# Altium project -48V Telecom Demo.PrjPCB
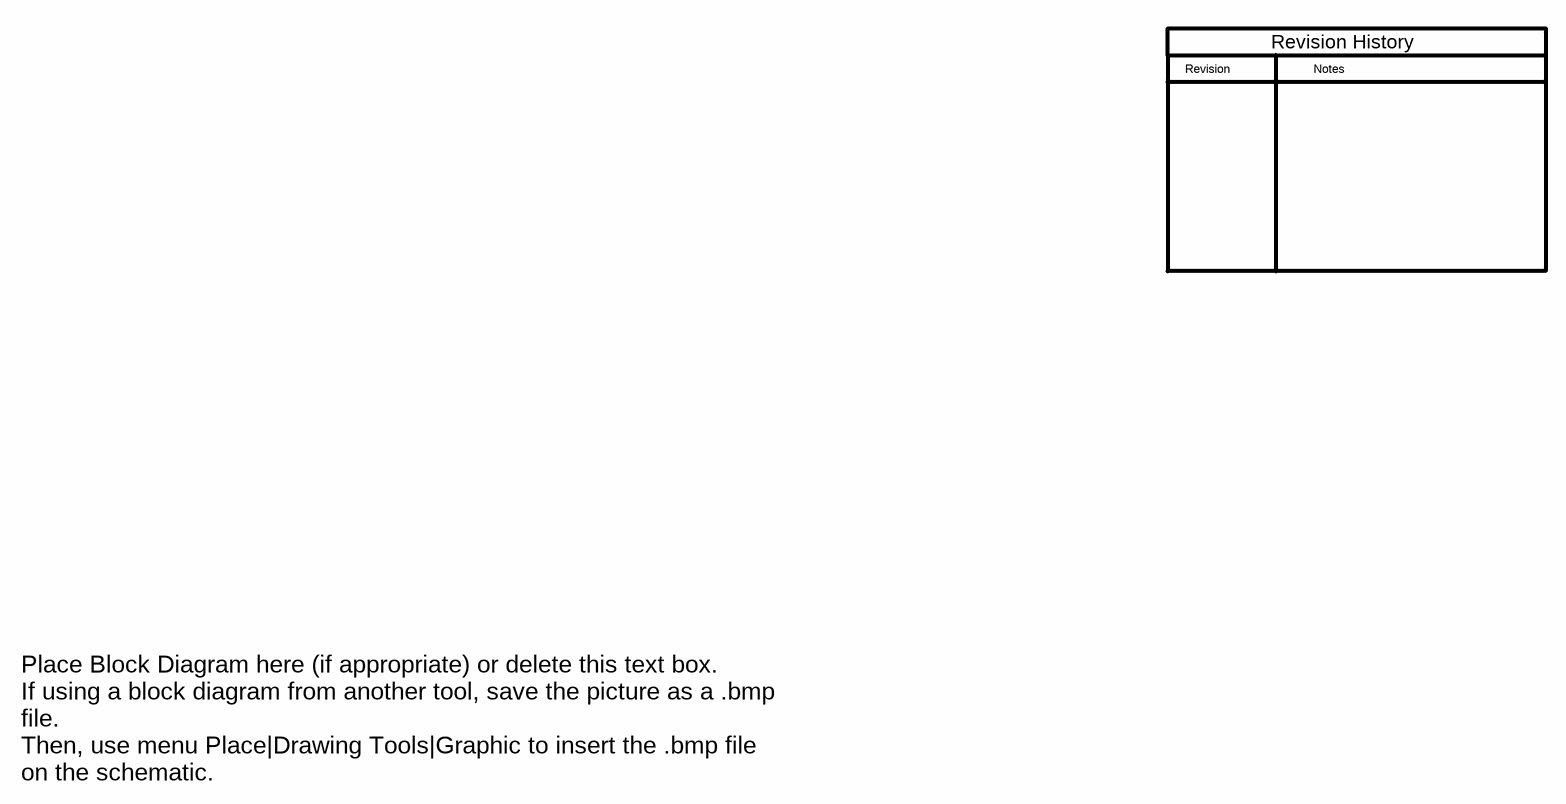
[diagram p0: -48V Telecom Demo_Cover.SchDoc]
TechSupport: http://e2e.ti.com; SCH_Rev: 0; PRJ_Title: TI Designs Precision; PRJ_Number: TIDA-00313; PRJ_Customer: Precision Analog; CopyrightYear: 2014
3 sheets, 61 parts. Net scope: flat (ports and power ports of the same name join across sheets).
Board file: -48V Telecom Demo.PcbDoc
Sheets:
  -48V Telecom Demo_Cover.SchDoc
  -48V Telecom Demo_Main.SchDoc
  -48V Telecom Demo_Hardware.SchDoc

## Sheet -48V Telecom Demo_Cover.SchDoc
size 431 x 279 mm; Date: Not shown in title block; ApprovedBy: Not shown in title block; CheckedBy: Not shown in title block; Author: Not shown in title block; CompanyName: Not shown in title block; Engineer: Not shown in title block; Organization: Not shown in title block; Address1: Not shown in title block; Address2: Not shown in title block; Address3: Not shown in title block; Address4: Not shown in title block; DocumentNumber: 1; Revision: Use project parameter SCH_Rev; SheetNumber: 1; SheetTotal: 1; PageSetup: Record=PageOptions|CenterHorizontal=True|CenterVertical=True|PrintScale=1.00|XCorrection=1.00|YCorrection=1.00|PrintKind=0|BorderSize=5000000|LeftOffset=0|BottomOffset=0|Orientation=2|PaperLength=1000|PaperWidth=1000|Scale=100|PaperSource=15|PrintQuality=600|MediaType=1|DitherType=10|PaperKind=Letter|PrintScaleMode=1

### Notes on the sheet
- Revision
- Notes
- Revision History
- Place Block Diagram here (if appropriate) or delete this text box.
  If using a block diagram from another tool, save the picture as a .bmp file.
  Then, use menu Place|Drawing Tools|Graphic to insert the .bmp file on the schematic.

## Sheet -48V Telecom Demo_Main.SchDoc: Schematic for TIDA-00313
size 431 x 279 mm; Date: Not shown in title block; ApprovedBy: Not shown in title block; CheckedBy: Not shown in title block; Author: Not shown in title block; CompanyName: Not shown in title block; Engineer: Not shown in title block; Organization: Not shown in title block; Address1: Not shown in title block; Address2: Not shown in title block; Address3: Not shown in title block; Address4: Not shown in title block; DocumentNumber: 1; Revision: Use project parameter SCH_Rev; SheetNumber: 1; SheetTotal: 1; PageSetup: Record=PageOptions|CenterHorizontal=True|CenterVertical=True|PrintScale=0.62|XCorrection=1.00|YCorrection=1.00|PrintKind=0|BorderSize=5000000|LeftOffset=0|BottomOffset=0|Orientation=2|PaperLength=1000|PaperWidth=1000|Scale=100|PaperSource=15|PrintQuality=600|MediaType=1|DitherType=10|PaperKind=Letter|PrintScaleMode=1
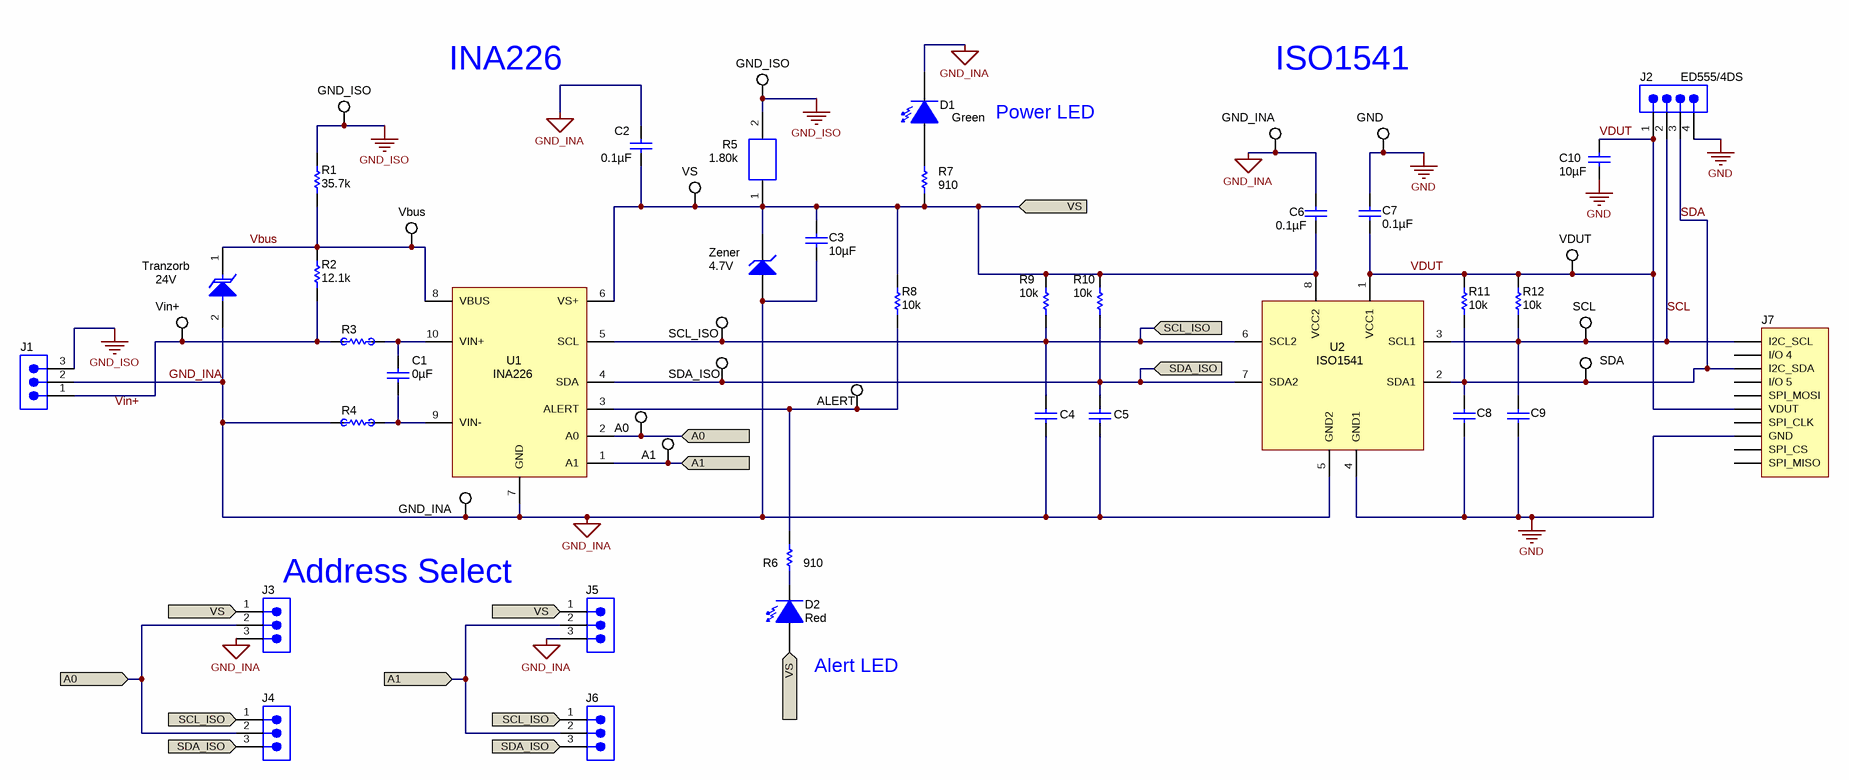
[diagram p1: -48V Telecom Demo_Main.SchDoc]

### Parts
C1  ValueDisplayed: 0µF  [0805_HV]  (hidden comment: 08055C104KAT2A)
C2  ValueDisplayed: 0.1µF  [0805_HV]  (hidden comment: 08055C104KAT2A)
C3  ValueDisplayed: 10µF  [0805_HV]  (hidden comment: C2012X5R1E106K125AB)
C4  06031A330JAT2A  [0603]  (value not drawn)
C5  06031A330JAT2A  [0603]  (value not drawn)
C6  ValueDisplayed: 0.1µF  [0805_HV]  (hidden comment: 08055C104KAT2A)
C7  ValueDisplayed: 0.1µF  [0805_HV]  (hidden comment: 08055C104KAT2A)
C8  06031A330JAT2A  [0603]  (value not drawn)
C9  06031A330JAT2A  [0603]  (value not drawn)
C10  ValueDisplayed: 10µF  [0805_HV]  (hidden comment: C2012X5R1E106K125AB)
D1  value Green  [LED_LTST-C190]  (hidden comment: LTST-C190GKT)
D2  value Red  [LED_LTST-C190_Red]  (hidden comment: LTST-C190CKT)
J1  ED555/3DS  [TERM_BLK_ED555-3DS]  (value not drawn)
J2  ED555/4DS  [TERM_BLK_ED555-4DS]
J3  TSW-103-07-G-S  [TSW-103-07-G-S]  (value not drawn)
J4  TSW-103-07-G-S  [TSW-103-07-G-S]  (value not drawn)
J5  TSW-103-07-G-S  [TSW-103-07-G-S]  (value not drawn)
J6  TSW-103-07-G-S  [TSW-103-07-G-S]  (value not drawn)
J7  851-43-010-20-001000  [851-43-010-20-001000]  (value not drawn)
R1  value 35.7k  [0805_HV]  (hidden comment: CRCW080535K7FKEA)
R2  value 12.1k  [0805_HV]  (hidden comment: CRCW080512K1FKEA)
R3  ax1206-1  [ax1206]  (value not drawn)
R4  ax1206-1  [ax1206]  (value not drawn)
R5  1.80k  [Resistor_4122]
R6  910  [3-0603]
R7  910  [3-0603]
R8  10k  [3-0603]
R9  10k  [3-0603]
R10  10k  [3-0603]
R11  10k  [3-0603]
R12  10k  [3-0603]
TP1  GND_INA  [Testpoint_Keystone_Compact]
TP2  GND_INA  [Testpoint_Keystone_Compact]
TP3  GND_ISO  [Testpoint_Keystone_Compact]
TP4  GND_ISO  [Testpoint_Keystone_Compact]
TP5  GND  [Testpoint_Keystone_Compact]
TP7  Vin+  [Testpoint_Keystone_Compact]
TP8  SCL_ISO  [Testpoint_Keystone_Compact]
TP9  SDA_ISO  [Testpoint_Keystone_Compact]
TP10  ALERT  [Testpoint_Keystone_Compact]
TP11  A0  [Testpoint_Keystone_Compact]
TP12  A1  [Testpoint_Keystone_Compact]
TP13  VDUT  [Testpoint_Keystone_Compact]
TP14  SCL  [Testpoint_Keystone_Compact]
TP15  SDA  [Testpoint_Keystone_Compact]
TP16  VS  [Testpoint_Keystone_Compact]
TP17  Vbus  [Testpoint_Keystone_Compact]
Tranzorb  value 24V  [SMB]  (hidden comment: SMBJ30A-13-F)
U1  INA226  [DGS0010A_M]
U2  ISO1541  [D0008A_N]
Zener  4.7V  [SOD-123]

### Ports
A0 (in), A1 (in), SCL_ISO (in), SDA_ISO (in), VS (in)

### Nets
GND: C7.2 C8.2 C9.2 C10.2 J2.4 J7.8(GND) TP5.1 U2.4(GND1)
GND_INA: C2.2 C3.2 C4.2 C5.2 C6.2 D1.2(K) J1.2 J3.3 J5.3 R4.1 TP1.1 TP2.1 Tranzorb.2(A) U1.7(GND) U2.5(GND2) Zener.1(A)
GND_ISO: J1.3 R1.2 R5.2 TP3.1 TP4.1
A0: J3.2 J4.2 TP11.1 U1.2(A0) ; port A0
A1: J5.2 J6.2 TP12.1 U1.1(A1) ; port A1
SCL: C9.1 J2.2 J7.1(I2C_SCL) R12.1 TP14.1 U2.3(SCL1)
SCL_ISO: C4.1 J4.1 J6.1 R9.1 TP8.1 U1.5(SCL) U2.6(SCL2) ; port SCL_ISO
SDA: C8.1 J2.3 J7.3(I2C_SDA) R11.1 TP15.1 U2.2(SDA1)
SDA_ISO: C5.1 J4.3 J6.3 R10.1 TP9.1 U1.4(SDA) U2.7(SDA2) ; port SDA_ISO
Vbus: R1.1 R2.2 TP17.1 Tranzorb.1(K) U1.8(VBUS)
VDUT: C7.1 C10.1 J2.1 J7.6(VDUT) R11.2 R12.2 TP13.1 U2.1(VCC1)
VS: C2.1 C3.1 C6.1 D2.1(A) J3.1 J5.1 R5.1 R7.2 R8.1 R9.2 R10.2 TP16.1 U1.6(VS+) U2.8(VCC2) Zener.2(K) ; port VS
NetC1_1: C1.1 R4.2 U1.9(VIN-)
NetC1_2: C1.2 R3.2 U1.10(VIN+)
NetD1_1: D1.1(A) R7.1
NetD2_2: D2.2(K) R6.1
NetJ1_1: J1.1 R2.1 R3.1 TP7.1
NetR6_2: R6.2 R8.2 TP10.1 U1.3(ALERT)

Not connected (* = marked no-connect by the designer): J7 2(I/O_4) 4(I/O_5) 5(SPI_MOSI) 7(SPI_CLK) 9(SPI_CS) 10(SPI_MISO)

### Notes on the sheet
- INA226
- Power LED
- ISO1541
- (near J3) Address Select
- (near D2) Alert LED
- Labels drawn without touching a wire or pin: Vin+

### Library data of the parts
C1 C2 C6 C7 = 08055C104KAT2A: CAP, CERM, 0.1uF, 50V, +/-10%, X7R, 0805; Manufacturer: AVX; Polarized: N; CompType: Capacitor; U/M: EA; Cap_F: 0.0000001; Tolerance_%: 10; ESR_Ohm: 0.024; Value1: 0.024 ohm; VDC_V: 50; TaMin_C: -55; TaMax_C: 125; Cap_Case: 0805
C3 C10 = C2012X5R1E106K125AB: CAP, CERM, 10uF, 25V, +/-10%, X5R, 0805; Manufacturer: TDK; Polarized: N; CompType: Capacitor; U/M: EA; Cap_F: 0.00001; Tolerance_%: 10; Value1: Unknown; VDC_V: 25; TaMin_C: -55; TaMax_C: 85; Cap_Case: 0805
C4 C5 C8 C9 = 06031A330JAT2A: CAP, CERM, 33pF, 100V, +/-5%, C0G/NP0, 0603; Manufacturer: AVX; Polarized: N; CompType: Capacitor; U/M: EA; Cap_F: 0.000000000033; Tolerance_%: 5; ESR_Ohm: 0.209; Value1: 0.209 ohm; VDC_V: 100; TaMin_C: -55; TaMax_C: 125
D1 = LTST-C190GKT: LED, Green, SMD; Manufacturer: Lite-On; Vf_V: 2.1; Value2: 2.1V; Io_A: 0.02; Power_TotalModule: 0.1; Value1: 0.1W; U/M: EA
D2 = LTST-C190CKT: LED, Red, SMD; Manufacturer: Lite-On; Vf_V: 2; Value2: 2V; Io_A: 0.02; Tjmax_C: 85; Power_TotalModule: 0.0625; Value1: 0.0625W; U/M: EA
J1 = ED555/3DS: Terminal Block, 6A, 3.5mm Pitch, 3-Pos, TH; Manufacturer: On-Shore Technology; SymbolCreator: a0799628; CompType: Connector; U/M: EA
J2 = ED555/4DS: Terminal Block, 6A, 3.5mm Pitch, 4-Pos, TH; Manufacturer: On-Shore Technology; SymbolCreator: a0412235; CompType: Connector; U/M: EA
J3-J6 = TSW-103-07-G-S: Header, TH, 100mil, 3x1, Gold plated, 230 mil above insulator; Manufacturer: Samtec; SymbolCreator: a0799628; U/M: EA
J7 = SM-USB-DIG-CONN: 10-Pin 50-mil Connector of SM-USB-DIG; Manufacturer: Mill-Max Manufacturing Corp.; SymbolCreator: Use LDAP id; CompType: Conn; U/M: EA, IN, or GM
R1 = CRCW080535K7FKEA: RES, 35.7k ohm, 1%, 0.125W, 0805; Manufacturer: Vishay-Dale; CompType: Resistor; Res_ohm: 35700; Value_Code: 35k7; Tolerance_%: 1; Power_W: 0.125; VDC_V: 150; TempCo: 100 ppm/C; EIA_Code: E96; U/M: EA
R2 = CRCW080512K1FKEA: RES, 12.1k ohm, 1%, 0.125W, 0805; Manufacturer: Vishay-Dale; CompType: Resistor; Res_ohm: 12100; Value_Code: 12k1; Tolerance_%: 1; Power_W: 0.125; VDC_V: 150; TempCo: 100 ppm/C; EIA_Code: E96; U/M: EA
R3 R4 = ax1206-2: RES, 1.00k ohm, 1%, 0.25W, 1206+axial; Manufacturer: Vishay-Dale; CompType: Resistor; Res_ohm: 1000; Value_Code: 1k00; Tolerance_%: 1; Power_W: 0.25; VDC_V: 200; TempCo: 100 ppm/C; EIA_Code: E96; U/M: EA
R5 = Resistor_4122: Manufacturer: TE Connectivity; PartNumber: 1-1879022-9; SymbolVersion: use current date i.e. 2008-05-20; SymbolCreator: Use a-id; CompType: Used in some BOM reports.  Useful for finding later.; U/M: EA, IN, or GM; Description: RES 1.80K OHM 3W 5% SMD
R6-R12 = ERJ3GE: Thick Film Chip Resistor, 1 Ohm to 10M Ohm Range, 5% Tolerance, 0603 Size, 0.1 W; Note: If flow soldering, adjust pad width of PCB Footprint to 0.7 - 0.8 times the width of the resistor.
TP1-TP5 TP7-TP17 = 5016: Test Point, Compact, SMT; Manufacturer: Keystone; CompType: Test Point Loop; U/M: EA
Tranzorb = SMBJ24A-13-F: Diode, TVS, Uni, 24V, 600W, SMB; Manufacturer: Diodes Inc.; U/M: EA; Power_W: 5; Vr_V: 24; Value1: 5W
U1 = INA226: Manufacturer: Used in BOM report; SymbolVersion: use current date i.e. 2008-05-20; SymbolCreator: Use a-id; CompType: Used in some BOM reports.  Useful for finding later.; U/M: EA, IN, or GM
U2 = ISO1541: Manufacturer: Used in BOM report; SymbolVersion: use current date i.e. 2008-05-20; SymbolCreator: Use a-id; CompType: Used in some BOM reports.  Useful for finding later.; U/M: EA, IN, or GM
Zener = BZT52C4V7: Surface Mount Zener Diode

## Sheet -48V Telecom Demo_Hardware.SchDoc
size 431 x 279 mm; Date: Not shown in title block; ApprovedBy: Not shown in title block; CheckedBy: Not shown in title block; Author: Not shown in title block; CompanyName: Not shown in title block; Engineer: Not shown in title block; Organization: Not shown in title block; Address1: Not shown in title block; Address2: Not shown in title block; Address3: Not shown in title block; Address4: Not shown in title block; DocumentNumber: 1; Revision: Use project parameter SCH_Rev; SheetNumber: 1; SheetTotal: 1; PageSetup: Record=PageOptions|CenterHorizontal=True|CenterVertical=True|PrintScale=1.00|XCorrection=1.00|YCorrection=1.00|PrintKind=0|BorderSize=5000000|LeftOffset=0|BottomOffset=0|Orientation=2|PaperLength=1000|PaperWidth=1000|Scale=100|PaperSource=15|PrintQuality=600|MediaType=1|DitherType=10|PaperKind=Letter|PrintScaleMode=1
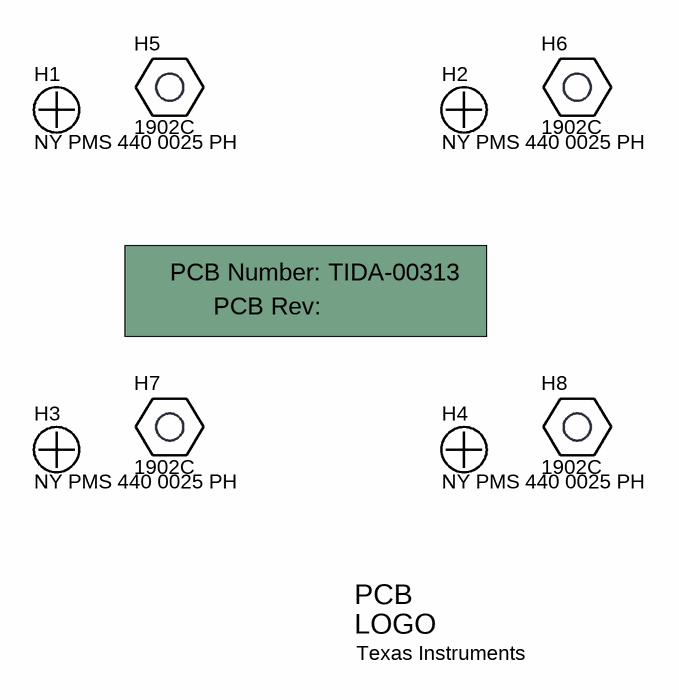
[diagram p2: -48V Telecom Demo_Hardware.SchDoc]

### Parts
!PCB  Printed Circuit Board  (value not drawn)  (mechanical)
H1  NY PMS 440 0025 PH  [NY PMS 440 0025 PH]
H2  NY PMS 440 0025 PH  [NY PMS 440 0025 PH]
H3  NY PMS 440 0025 PH  [NY PMS 440 0025 PH]
H4  NY PMS 440 0025 PH  [NY PMS 440 0025 PH]
H5  1902C  [Keystone_1902C]
H6  1902C  [Keystone_1902C]
H7  1902C  [Keystone_1902C]
H8  1902C  [Keystone_1902C]
Logo1  Texas Instruments  [TI_Symbol_Overlay_Small]  (no BOM)

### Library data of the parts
!PCB = PCB: Manufacturer: Any; PartNumber: TIDA-00313; SymbolCreator: a0412235
H1-H4 = NY PMS 440 0025 PH: Machine Screw, Round, #4-40 x 1/4, Nylon, Philips panhead; Manufacturer: B&F Fastener Supply; CompType: Hardware; SymbolCreator: codlsc; U/M: EA
H5-H8 = 1902C: Standoff, Hex, 0.5"L #4-40 Nylon; Manufacturer: Keystone; CompType: Hardware
Logo1 = TI_Logo: Texas Instrument Corporate Signature; SymbolCreator: codlsc

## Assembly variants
001: all parts fitted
